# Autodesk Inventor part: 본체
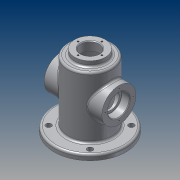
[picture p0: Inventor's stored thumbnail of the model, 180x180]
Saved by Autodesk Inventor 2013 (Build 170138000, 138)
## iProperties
Created: 2014-12
Part Number: 본체
Material: 알루미늄 6061
Document SubType Name: Modeling
Designer: SD
Density: 2.71 g/cm^3
Mass: 478.682 g
Surface Area: 609.625 cm^2
Volume: 176.636 cm^3
Author: SD
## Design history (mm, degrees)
sketch "스케치1"
  geometry: C1 r 32.5 at (0, 0); C2 r 52.5 at (0, 0); 1 further point
  constraints: 2 centre point, 2 coincident
  dimensions: "d0" = 65 diameter of C1; "d1" = 105 diameter of C2
extrude "돌출1" new body sketch "스케치1" distance "d3" = 98; taper "d4" = 0 deg
fillet "모깎기1" dims "d5" = 3
feature "쉘1" dims "d6" = 5
extrude "돌출2" join sketch "스케치1" distance "d7" = 8; taper "d8" = 0 deg
sketch "스케치2"
  geometry: C1 r 22.5 at (0, 0); 1 further point
  constraints: 1 centre point, 1 coincident
  dimensions: "d9" = 45 diameter of C1
extrude "돌출3" join sketch "스케치2" distance "d10" = 8; taper "d11" = 0 deg
node "작업 평면1"
node "작업 평면2"
sketch "스케치5"
  geometry: L1 (-52.5, 0)-(52.5, 0) reference; C1 r 25 at (0, 55); 1 further point
  constraints: 1 centre point, 1 vertical alignment
  dimensions: "d14" = 50 diameter of C1; "d15" = 55 distance from line of L1 C1.centre
extrude "돌출4" join sketch "스케치5" stored distance "d16" = 8; taper "d17" = 0 deg
hole "구멍1" diameter "d20" = 25; stored, may be unused: countersink angle "d24" = 90 deg, drill point angle "d26" = 0 deg; dims "d18" = 10, "d19" = 10, "d21" = 6, "d22" = 32, "d23" = 12, "d25" = 42.5
sketch "스케치6"
  geometry: C1 r 25 at (0, 0) reference; 2 further points
  constraints: 1 horizontal alignment
  dimensions: "d28" = 20.5 distance of point (-20.5, 0) C1.centre
hole "구멍2" sketch "스케치6" at (-20.5, 0) diameter "d29" = 2.459; stored, may be unused: countersink angle "d33" = 90 deg, drill point angle "d35" = 118 deg; dims "d30" = 6, "d31" = 32, "d32" = 12, "d34" = 8
fillet "모깎기3" dims "d39" = 0.3
chamfer "모따기1" distance "d40" = 1; stored, may be unused: second distance "d41" = 2, angle "d42" = 45 deg
hole "구멍3" diameter "d45" = 27; stored, may be unused: countersink angle "d49" = 90 deg, drill point angle "d51" = 118 deg; dims "d43" = 10, "d44" = 10, "d46" = 6, "d47" = 4, "d48" = 2, "d50" = 8
sketch "스케치7"
  geometry: 2 further points
  constraints: 1 vertical alignment
  dimensions: "d52" = 17.5 distance of point (0, 0) point (0, 17.5)
hole "구멍4" sketch "스케치7" at (0, 17.5) diameter "d53" = 2.459; stored, may be unused: countersink angle "d57" = 90 deg, drill point angle "d59" = 118 deg; dims "d54" = 6, "d55" = 4, "d56" = 2, "d58" = 8
chamfer "모따기2" distance "d63" = 1; stored, may be unused: second distance "d64" = 2, angle "d65" = 45 deg
sketch "스케치8" dims "d67" = 86
  geometry: L1 (0, 0)-(30.406, 30.406); L2 (0, 0)-(43, 0); C1 r 4 at (30.406, 30.406); 1 further point
  constraints: 4 end point, 2 coincident, 1 centre point, 1 equal length, 1 horizontal, 3 other
  dimensions: "d68" = 45 deg angle of L2 L1; "d69" = 8 diameter of C1
extrude "돌출5" cut sketch "스케치8" stored distance "d70" = 10; taper "d71" = 0 deg
node "작업 평면3"
sketch "스케치9"
  geometry: L1 (-29.5, 98)-(29.5, 98) reference; 2 further points
  constraints: 1 vertical alignment, 1 other
  dimensions: "d75" = 9 distance from line of L1 point (0, 89)
feature "엠보싱1" sketch "스케치9" dims "d14" = 50, "d76" = 1, "d77" = 0
fillet "모깎기4" dims "d78" = 3
fillet "모깎기5" dims "d79" = 3
node "솔리드1"
pattern_circular "원형 패턴1" dims angle "d37" = 360 deg
mirror "대칭1"
pattern_circular "원형 패턴2" dims angle "d61" = 360 deg
pattern_circular "원형 패턴3" dims angle "d73" = 360 deg
node "투영된 루프1"
other parameters: "d12" = 55, "d13" = 42.5
